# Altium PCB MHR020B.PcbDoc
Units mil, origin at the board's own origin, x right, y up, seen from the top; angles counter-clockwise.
Board outline 3200 x 2500 mil, 2 copper layers (Top Layer, Bottom Layer), stack 62 mil thick; 118 components, 36 nets, 183 pads, 20 vias.
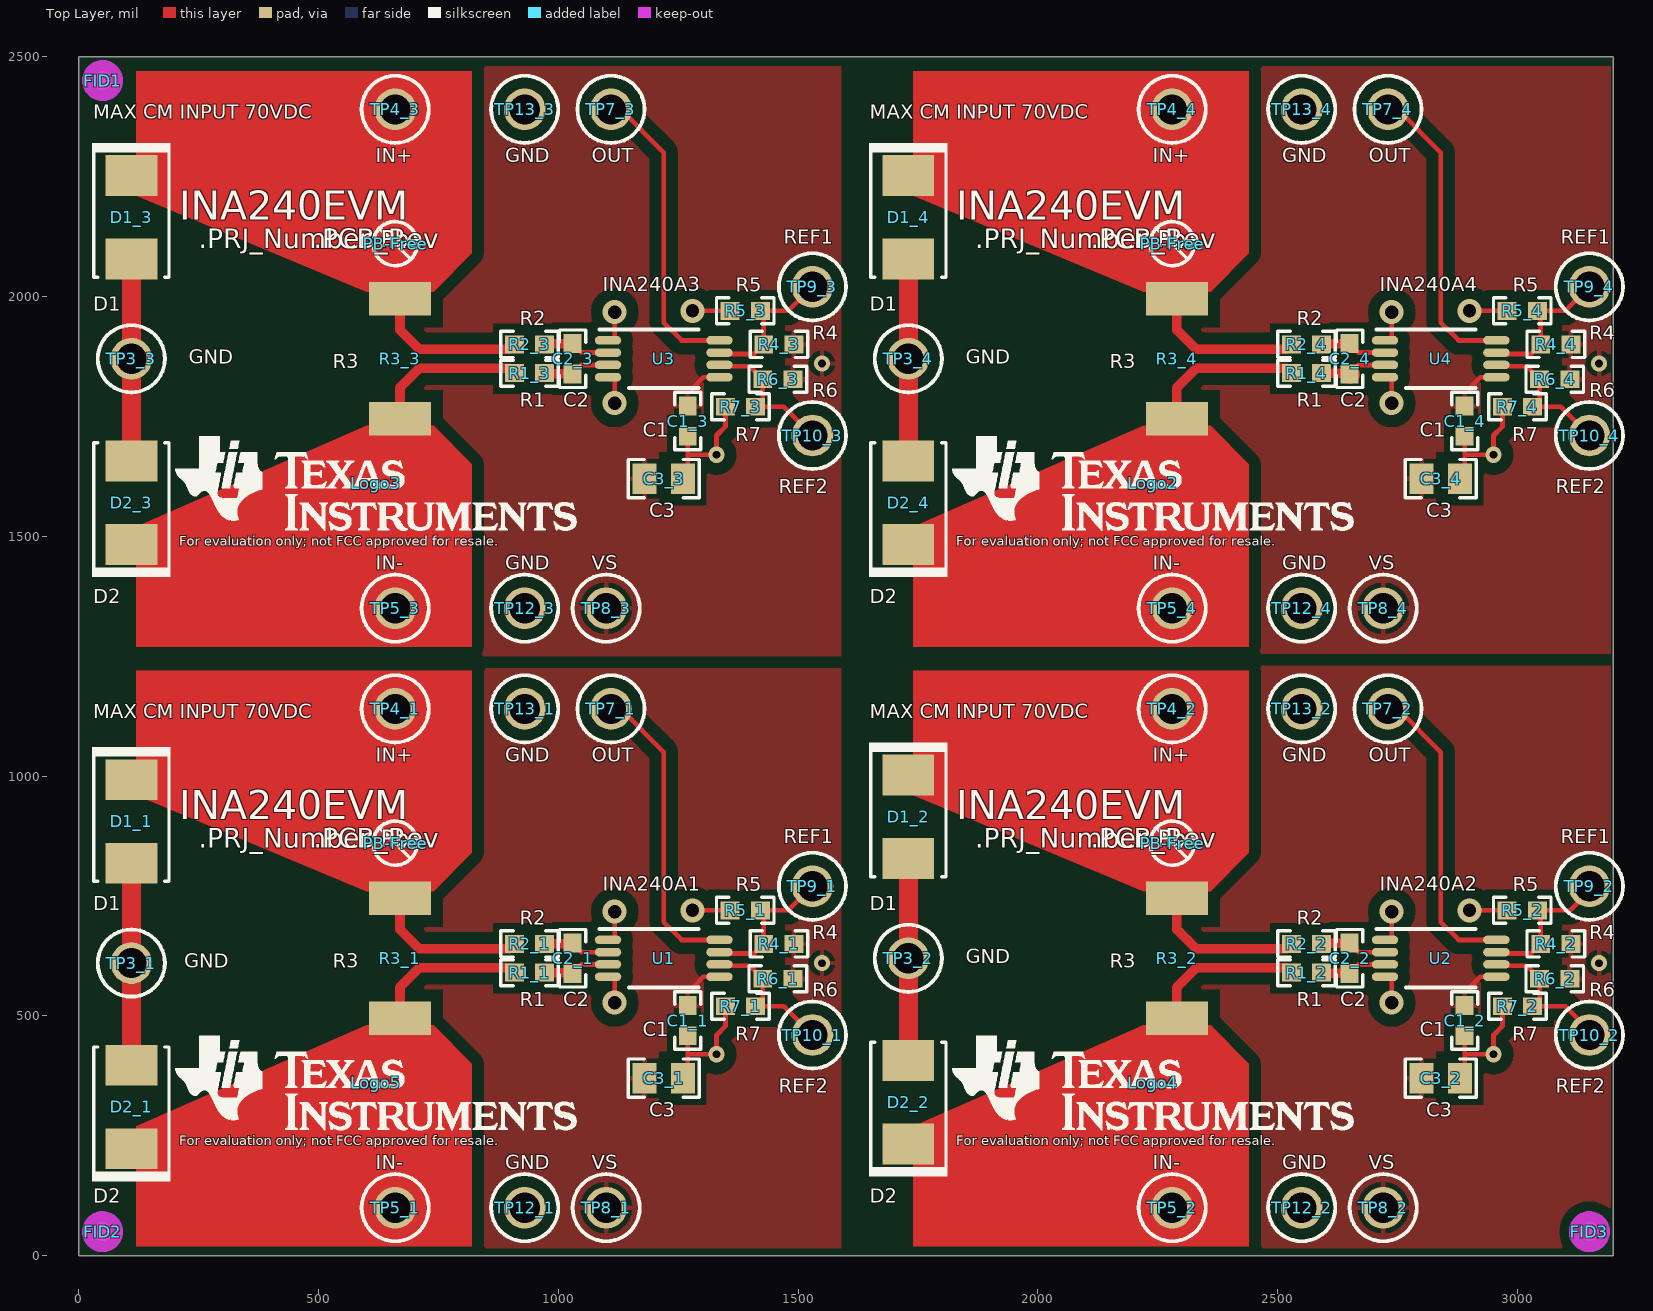
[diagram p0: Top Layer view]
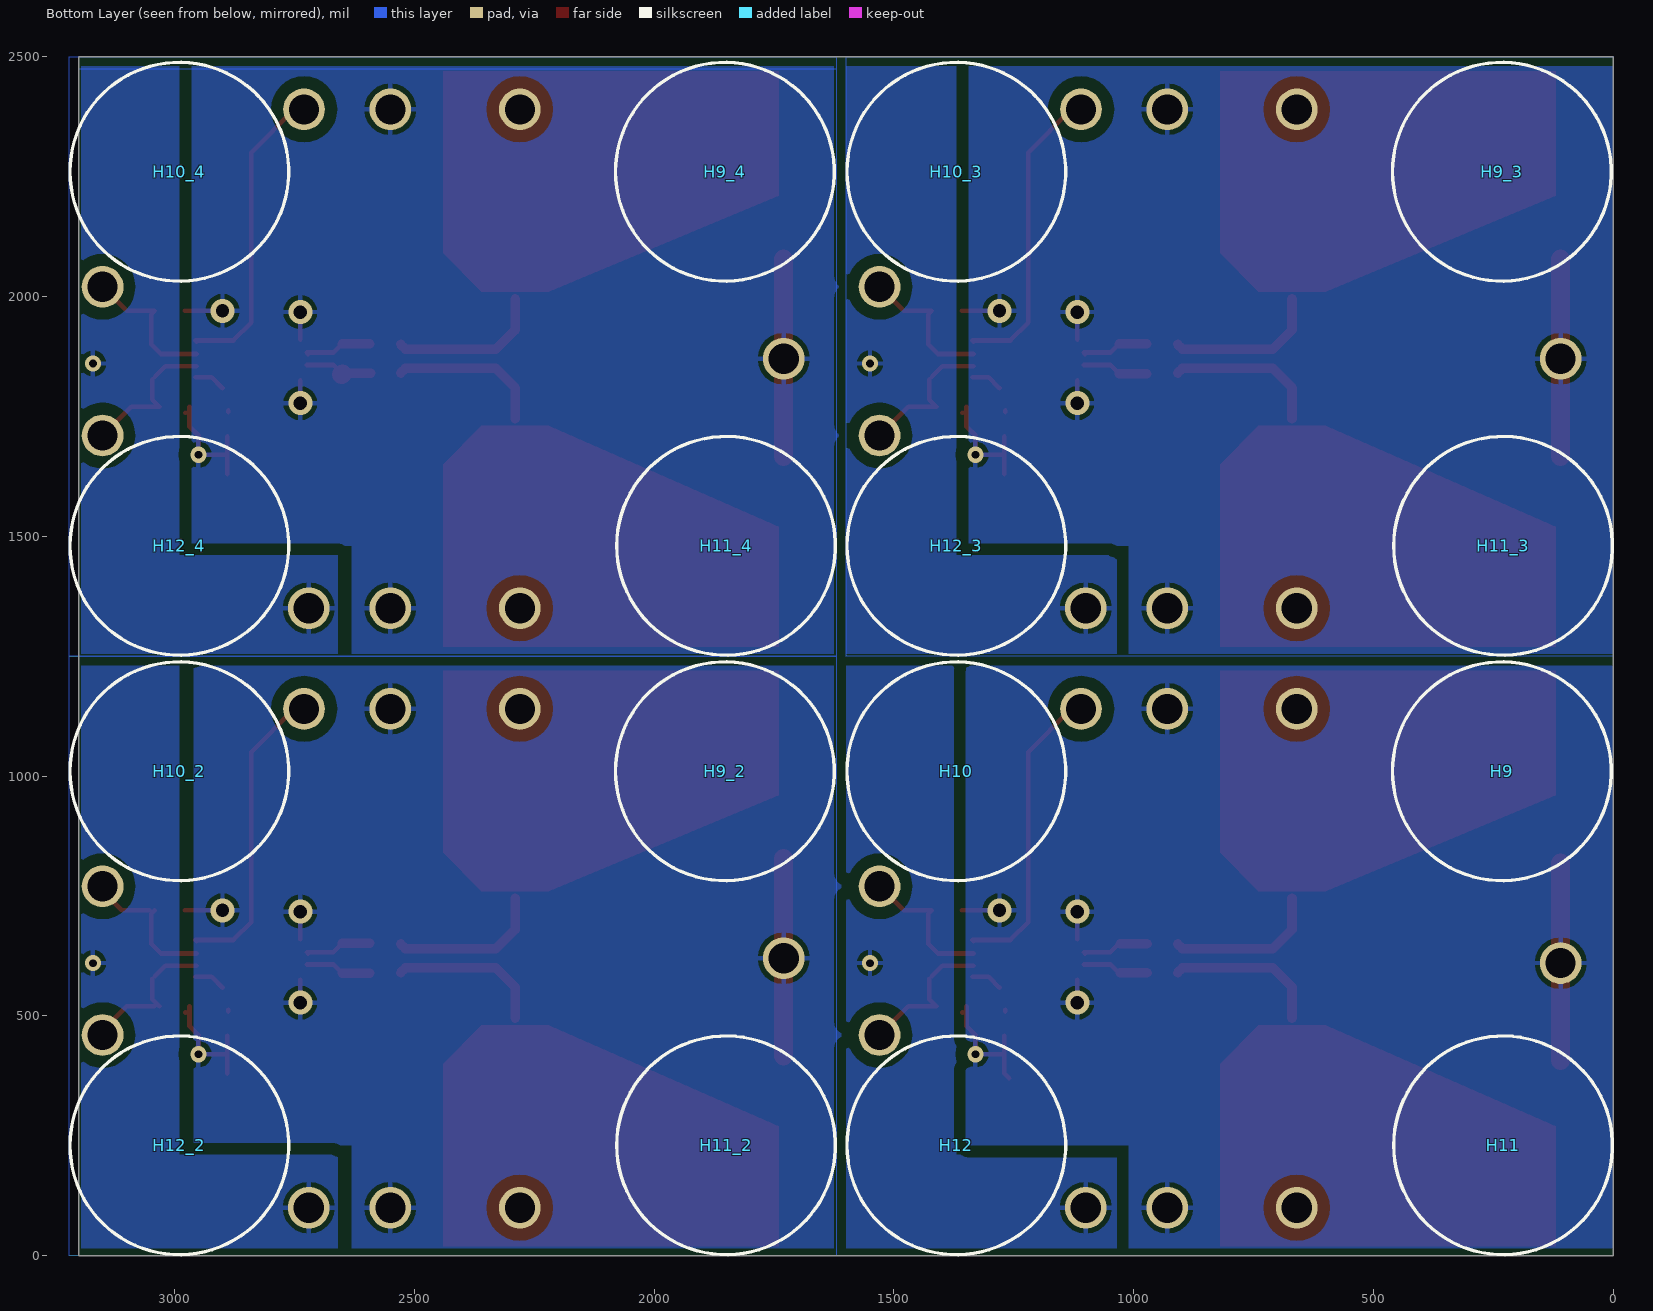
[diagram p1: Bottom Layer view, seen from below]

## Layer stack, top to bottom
Top Solder: solder mask 0.4, Solder Resist, Dk 3.5
Top Layer: signal copper 1.4
Dielectric1: core 59.2, FR-4, Dk 4.8
Bottom Layer: signal copper 1.4
Bottom Solder: solder mask 0.4, Solder Resist, Dk 3.5

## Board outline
0,0 3200,0 3200,2500 0,2500 0,0

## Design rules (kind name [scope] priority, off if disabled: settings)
AcuteAngle [All] p1: minimum=4.50000000000000E+0001 checktracksonly=FALSE
AssemblyTestPointUsage [All] p1: valid=2
Clearance Clearance_Keepouts [((IsTrack Or IsArc) And Not InPoly) And IsFree and IsKeepOut vs ((IsTrack Or IsArc) And Not InPoly) And IsFree and IsKeepOut] p1: gap=0
Clearance Clearance_BoardEdge_MountingHoles [OnCopper and InComponentClass('Mounting Holes') vs IsKeepOut] p2: gap=20
Clearance Clearance_BoardEdge_Poly [OnCopper and InPoly vs IsKeepOut] p3: gap=20
Clearance Clearance_BoardEdge [OnCopper and Not InComponentClass('Logo') and not InComponentClass('FiducialMark') and not InRegion(1000,500,4000,800) and Not IsKeepout vs IsKeepOut] p4: gap=20
Clearance Clearance_Poly [InPolygon] p5: gap=25
Clearance [All] p6: gap=7.87
ComponentClearance ComponentClearance_MountingHoles_FiducialMarks [InComponentClass('Mounting Holes') vs InComponentClass('FiducialMark')] p1: gap=10 collisioncheckmode=3 verticalgap=10 showdistances=FALSE
ComponentClearance ComponentClearance_Shunt [InComponentClass('Header') vs InComponentClass('Shunt')] p2: gap=0 collisioncheckmode=3 verticalgap=0 showdistances=FALSE
ComponentClearance ComponentClearance_Logo [InComponentClass('Logo')] p3: gap=10 collisioncheckmode=3 verticalgap=10 showdistances=FALSE
ComponentClearance ComponentClearance_ScrewToNut [(HasFootprint('NY PMS 440 0025 PH')) vs (HasFootprint('Keystone_1902C'))] p4: gap=5 collisioncheckmode=3 verticalgap=10 showdistances=FALSE
ComponentClearance ComponentClearance_MountingHoles [InComponentClass('Mounting Holes')] p5: gap=10 collisioncheckmode=3 verticalgap=100000 showdistances=FALSE
ComponentClearance ComponentClearance_SmallPassives [HasFootprint('0201*') or HasFootprint('0402*') or HasFootprint('0508') or HasFootprint('0603*') or HasFootprint('0612') or HasFootprint('0805*') or HasFootprint('0815*') or HasFootprint('0830*') or HasFootprint('1206*') or HasFootprint('1210*') or HasFootprint('1808*') or HasFootprint('1812*') or HasFootprint('1825*') or HasFootprint('2010*') or HasFootprint('2220*') or HasFootprint('2225*') or HasFootprint('2512*') or HasFootprint('2728*') or HasFootprint('3518*') vs HasFootprint('0201*') or HasFootprint('0402*') or HasFootprint('0508') or HasFootprint('0603*') or HasFootprint('0612') or HasFootprint('0805*') or HasFootprint('0815*') or HasFootprint('0830*') or HasFootprint('1206*') or HasFootprint('1210*') or HasFootprint('1808*') or HasFootprint('1812*') or HasFootprint('1825*') or HasFootprint('2010*') or HasFootprint('2220*') or HasFootprint('2225*') or HasFootprint('2512*') or HasFootprint('2728*') or HasFootprint('3518*')] p6: gap=20 collisioncheckmode=3 verticalgap=10 showdistances=FALSE
ComponentClearance ComponentClearance_THtoSMT [IsThruComponent vs IsSMTComponent] p7: gap=10 collisioncheckmode=3 verticalgap=30 showdistances=FALSE
ComponentClearance ComponentClearance_THtoTH [IsThruComponent vs IsThruComponent] p8: gap=20 collisioncheckmode=3 verticalgap=30 showdistances=FALSE
ComponentClearance [All] p9: gap=10 collisioncheckmode=3 verticalgap=10 showdistances=FALSE
DiffPairsRouting [All] p1: maxlimit=100 minlimit=10 mostfreqgap=10 toplayer_minwidth=15 toplayer_maxwidth=15 toplayer_prefwidth=15 bottomlayer_minwidth=15 bottomlayer_maxwidth=15 bottomlayer_prefwidth=15 maxuncoupledlength=1000
FabricationTestPointUsage TestPointUsage [All] p1: valid=2 allowmultiple=FALSE
FabricationTestpoint Testpoint [All] p1: side=3 testpointundercomponent=TRUE minsize=40 maxsize=100 preferedsize=60 minholesize=0 maxholesize=40 preferedholesize=32 testpointgrid=1 allowsidetop=TRUE allowsidebottom=TRUE usegrid=TRUE gridtolerance=0.01
FanoutControl Fanout_LCC [IsLCC] p1: bgadir=Out bgaviamode=Centered fanoutstyle=Auto fanoutdirection=Alternating viagrid=1 // Fanout_LCC (Default Rule)
FanoutControl Fanout_BGA [IsBGA] p2: bgadir=Out bgaviamode=Centered fanoutstyle=Auto fanoutdirection=Alternating viagrid=1 // Fanout_BGA (Default Rule)
FanoutControl Fanout_Default [All] p4: bgadir=Out bgaviamode=Centered fanoutstyle=Auto fanoutdirection=Alternating viagrid=1 // Fanout_Default (Default Rule)
FanoutControl Fanout_Small [(CompPinCount < 5)] p5: bgadir=Out bgaviamode=Centered fanoutstyle=Auto fanoutdirection=OutThenIn viagrid=1 // Fanout_Small (Default Rule)
HoleSize [All] p1: absolutevalues=TRUE maxlimit=251 minlimit=8 maxpercent=80.000 minpercent=20.000
MinimumAnnularRing MinimumAnnularRing_ThermalPadVias [IsVia and InAnyComponent] p1: minimumring=5.91
MinimumAnnularRing [All] p2: minimumring=9
MinimumSolderMaskSliver MinimumSolderMaskSliver_Logo [InComponentClass('Logo') vs InComponentClass('Logo')] p1: minsoldermaskwidth=0.7
MinimumSolderMaskSliver [All] p2: minsoldermaskwidth=3.94
PlaneConnect [All] p1: planeconnectstyle=Relief reliefexpansion=10 reliefentries=4 reliefconductorwidth=10 reliefairgap=10
PolygonConnect [All] p1: connectstyle=Relief reliefconductorwidth=10 reliefentries=4 polygonreliefangle="90 Angle" airgapwidth=10
RoutingVias ThermalPadVias [IsVia and InAnyComponent] p1: holewidth=7.87 width=19.68 viastyle="Through Hole" minholewidth=7.87 minwidth=19.68 maxholewidth=12.99 maxwidth=23.62
RoutingVias [All] p2: holewidth=16 width=34 viastyle="Through Hole" minholewidth=7.87 minwidth=26 maxholewidth=40 maxwidth=65
SilkToBoardRegionClearance [Not ((IsComment or IsDesignator) And (Hide <> 'False')) and not InRegion(1000,500,4000,800)] p1:
SilkToSilkClearance SilkToSilkClearance_Pb-FreeLogo [(HasFootprint('Pb-Free_Overlay_Medium') OR HasFootprint('Pb-Free_Overlay_Small')) vs (HasFootprint('Pb-Free_Overlay_Medium') OR HasFootprint('Pb-Free_Overlay_Small'))] p1: silktosilkclearance=0
SilkToSilkClearance [All] p2: silktosilkclearance=5
SilkToSolderMaskClearance "Silk to Solder Mask Opening" [All] p1: minsilkscreentomaskgap=3 clearancetoexposedcopper=FALSE
SolderMaskExpansion [All] p1: expansion=1.97
Width [All] p1: maxlimit=100 minlimit=10 preferedwidth=10
15 further rules are at their usual default settings.

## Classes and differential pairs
component class MHR020A_Hardware: FID1 FID2 FID3 H9 H9_2 H9_3 H9_4 H10 H10_2 H10_3 H10_4 H11 H11_2 H11_3 H11_4 H12 H12_2 H12_3 H12_4 Logo2 Logo3 Logo4 Logo5 PB-Free ZZ2 ZZ3 ZZ4
component class FiducialMark: FID1 FID2 FID3
component class AssemblyNote: ZZ2 ZZ3 ZZ4
component class Logo: Logo2 Logo3 Logo4 Logo5
component class MHR020A: C1_1 C1_2 C1_3 C1_4 C2_1 C2_2 C2_3 C2_4 C3_1 C3_2 C3_3 C3_4 D1_1 D1_2 D1_3 D1_4 D2_1 D2_2 D2_3 D2_4 R1_1 R1_2 R1_3 R1_4 R2_1 R2_2 R2_3 R2_4 R3_1 R3_2 R3_3 R3_4 R4_1 R4_2 R4_3 R4_4 R5_1 R5_2 R5_3 R5_4 R6_1 R6_2 R6_3 R6_4 R7_1 R7_2 R7_3 R7_4 TP3_1 TP3_2 TP3_3 TP3_4 TP4_1 TP4_2 TP4_3 TP4_4 TP5_1 TP5_2 TP5_3 TP5_4 TP7_1 TP7_2 TP7_3 TP7_4 TP8_1 TP8_2 TP8_3 TP8_4 TP9_1 TP9_2 TP9_3 TP9_4 TP10_1 TP10_2 TP10_3 TP10_4 TP12_1 TP12_2 TP12_3 TP12_4 TP13_1 TP13_2 TP13_3 TP13_4 U1 U2 U3 U4

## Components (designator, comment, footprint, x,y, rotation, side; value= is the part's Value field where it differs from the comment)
C1_1 "0603YC104JAT2A" 0603 1270,490 r270 top
C1_2 "0603YC104JAT2A" 0603 2890,490 r270 top
C1_3 "0603YC104JAT2A" 0603 1270,1740 r270 top
C1_4 "0603YC104JAT2A" 0603 2890,1740 r270 top
C2_1 "0603YC104JAT2A" 0603 1030,620 r90 top
C2_2 "0603YC104JAT2A" 0603 2650,620 r90 top
C2_3 "0603YC104JAT2A" 0603 1030,1870 r90 top
C2_4 "0603YC104JAT2A" 0603 2650,1870 r90 top
C3_1 "08053D105KAT2A" 0805_HV 1220,370 r0 top
C3_2 "08053D105KAT2A" 0805_HV 2840,370 r0 top
C3_3 "08053D105KAT2A" 0805_HV 1220,1620 r0 top
C3_4 "08053D105KAT2A" 0805_HV 2840,1620 r0 top
D1_1 "SMBJ70A-13-F" SMB 110,905.27 r270 top
D1_2 "SMBJ70A-13-F" SMB 1730,915.27 r270 top
D1_3 "SMBJ70A-13-F" SMB 110,2165.27 r270 top
D1_4 "SMBJ70A-13-F" SMB 1730,2165.27 r270 top
D2_1 "SMBJ70A-13-F" SMB 110,310 r90 top
D2_2 "SMBJ70A-13-F" SMB 1730,320 r90 top
D2_3 "SMBJ70A-13-F" SMB 110,1570 r90 top
D2_4 "SMBJ70A-13-F" SMB 1730,1570 r90 top
FID1 "Fiducial" Fiducial10-20 50,2450 r0 top
FID2 "Fiducial" Fiducial10-20 50,50 r0 top
FID3 "Fiducial" Fiducial10-20 3150,50 r0 top
H9 "SJ-5303 (CLEAR)" Bumpon_SJ5003Transparent 232.5,1010 r180 bottom
H9_2 "SJ-5303 (CLEAR)" Bumpon_SJ5003Transparent 1852.5,1010 r180 bottom
H9_3 "SJ-5303 (CLEAR)" Bumpon_SJ5003Transparent 232.5,2260 r180 bottom
H9_4 "SJ-5303 (CLEAR)" Bumpon_SJ5003Transparent 1852.5,2260 r180 bottom
H10 "SJ-5303 (CLEAR)" Bumpon_SJ5003Transparent 1370,1010 r180 bottom
H10_2 "SJ-5303 (CLEAR)" Bumpon_SJ5003Transparent 2990,1010 r180 bottom
H10_3 "SJ-5303 (CLEAR)" Bumpon_SJ5003Transparent 1370,2260 r180 bottom
H10_4 "SJ-5303 (CLEAR)" Bumpon_SJ5003Transparent 2990,2260 r180 bottom
H11 "SJ-5303 (CLEAR)" Bumpon_SJ5003Transparent 230,230 r180 bottom
H11_2 "SJ-5303 (CLEAR)" Bumpon_SJ5003Transparent 1850,230 r180 bottom
H11_3 "SJ-5303 (CLEAR)" Bumpon_SJ5003Transparent 230,1480 r180 bottom
H11_4 "SJ-5303 (CLEAR)" Bumpon_SJ5003Transparent 1850,1480 r180 bottom
H12 "SJ-5303 (CLEAR)" Bumpon_SJ5003Transparent 1370,230 r180 bottom
H12_2 "SJ-5303 (CLEAR)" Bumpon_SJ5003Transparent 2990,230 r180 bottom
H12_3 "SJ-5303 (CLEAR)" Bumpon_SJ5003Transparent 1370,1480 r180 bottom
H12_4 "SJ-5303 (CLEAR)" Bumpon_SJ5003Transparent 2990,1480 r180 bottom
Logo2 "Texas Instruments" TI_Stacked_Overlay_Small 2240,1610 r0 top
Logo3 "Texas Instruments" TI_Stacked_Overlay_Small 620,1610 r0 top
Logo4 "Texas Instruments" TI_Stacked_Overlay_Small 2240,360 r0 top
Logo5 "Texas Instruments" TI_Stacked_Overlay_Small 620,360 r0 top
PB-Free "Pb-Free Symbol" Pb-Free_Overlay_Small 2280,2110 r0 top
PB-Free "Pb-Free Symbol" Pb-Free_Overlay_Small 660,2110 r0 top
PB-Free "Pb-Free Symbol" Pb-Free_Overlay_Small 2280,860 r0 top
PB-Free "Pb-Free Symbol" Pb-Free_Overlay_Small 660,860 r0 top
R1_1 "ERJ-3GEY0R00V" 0603 940,590 r0 top
R1_2 "ERJ-3GEY0R00V" 0603 2560,590 r0 top
R1_3 "ERJ-3GEY0R00V" 0603 940,1840 r0 top
R1_4 "ERJ-3GEY0R00V" 0603 2560,1840 r0 top
R2_1 "ERJ-3GEY0R00V" 0603 940,650 r0 top
R2_2 "ERJ-3GEY0R00V" 0603 2560,650 r0 top
R2_3 "ERJ-3GEY0R00V" 0603 940,1900 r0 top
R2_4 "ERJ-3GEY0R00V" 0603 2560,1900 r0 top
R3_1 "STD" R2512 670,620 r270 top
R3_2 "STD" R2512 2290,620 r270 top
R3_3 "STD" R2512 670,1870 r270 top
R3_4 "STD" R2512 2290,1870 r270 top
R4_1 "ERJ-3GEY0R00V" 0603 1460,650 r180 top
R4_2 "ERJ-3GEY0R00V" 0603 3080,650 r180 top
R4_3 "ERJ-3GEY0R00V" 0603 1460,1900 r180 top
R4_4 "ERJ-3GEY0R00V" 0603 3080,1900 r180 top
R5_1 "ERJ-3GEY0R00V" 0603 1390,720 r180 top
R5_2 "ERJ-3GEY0R00V" 0603 3010,720 r180 top
R5_3 "ERJ-3GEY0R00V" 0603 1390,1970 r180 top
R5_4 "ERJ-3GEY0R00V" 0603 3010,1970 r180 top
R6_1 "ERJ-3GEY0R00V" 0603 1457.81,577.34 r180 top
R6_2 "ERJ-3GEY0R00V" 0603 3077.81,577.34 r180 top
R6_3 "ERJ-3GEY0R00V" 0603 1457.81,1827.34 r180 top
R6_4 "ERJ-3GEY0R00V" 0603 3077.81,1827.34 r180 top
R7_1 "ERJ-3GEY0R00V" 0603 1380,520 r180 top
R7_2 "ERJ-3GEY0R00V" 0603 3000,520 r180 top
R7_3 "ERJ-3GEY0R00V" 0603 1380,1770 r180 top
R7_4 "ERJ-3GEY0R00V" 0603 3000,1770 r180 top
TP3_1 "5012" Keystone5012 110,610 r90 top
TP3_2 "5012" Keystone5012 1730,620 r90 top
TP3_3 "5012" Keystone5012 110,1870 r90 top
TP3_4 "5012" Keystone5012 1730,1870 r90 top
TP4_1 "5012" Keystone5012 660,1140 r90 top
TP4_2 "5012" Keystone5012 2280,1140 r90 top
TP4_3 "5012" Keystone5012 660,2390 r90 top
TP4_4 "5012" Keystone5012 2280,2390 r90 top
TP5_1 "5012" Keystone5012 660,100 r90 top
TP5_2 "5012" Keystone5012 2280,100 r90 top
TP5_3 "5012" Keystone5012 660,1350 r90 top
TP5_4 "5012" Keystone5012 2280,1350 r90 top
TP7_1 "5012" Keystone5012 1110,1140 r90 top
TP7_2 "5012" Keystone5012 2730,1140 r90 top
TP7_3 "5012" Keystone5012 1110,2390 r90 top
TP7_4 "5012" Keystone5012 2730,2390 r90 top
TP8_1 "5012" Keystone5012 1100,100 r90 top
TP8_2 "5012" Keystone5012 2720,100 r90 top
TP8_3 "5012" Keystone5012 1100,1350 r90 top
TP8_4 "5012" Keystone5012 2720,1350 r90 top
TP9_1 "5012" Keystone5012 1530,770 r90 top
TP9_2 "5012" Keystone5012 3150,770 r90 top
TP9_3 "5012" Keystone5012 1530,2020 r90 top
TP9_4 "5012" Keystone5012 3150,2020 r90 top
TP10_1 "5012" Keystone5012 1530,460 r90 top
TP10_2 "5012" Keystone5012 3150,460 r90 top
TP10_3 "5012" Keystone5012 1530,1710 r90 top
TP10_4 "5012" Keystone5012 3150,1710 r90 top
TP12_1 "5012" Keystone5012 930,100 r90 top
TP12_2 "5012" Keystone5012 2550,100 r90 top
TP12_3 "5012" Keystone5012 930,1350 r90 top
TP12_4 "5012" Keystone5012 2550,1350 r90 top
TP13_1 "5012" Keystone5012 930,1140 r90 top
TP13_2 "5012" Keystone5012 2550,1140 r90 top
TP13_3 "5012" Keystone5012 930,2390 r90 top
TP13_4 "5012" Keystone5012 2550,2390 r90 top
U1 "INA240A1PW" PW0008A_N 1220,620 r0 top
U2 "INA240A2PW" PW0008A_N 2840,620 r0 top
U3 "INA240A3PW" PW0008A_N 1220,1870 r0 top
U4 "INA240A4PW" PW0008A_N 2840,1870.01 r0 top
ZZ2 "These assemblies are ESD sensitive, ESD precautions shall be observed." AssemblyNote 185,3829.11 r0 top
ZZ3 "These assemblies must be clean and free from flux and all contaminants. Use of no clean flux is not acceptable." AssemblyNote 185,3740.56 r0 top
ZZ4 "These assemblies must comply with workmanship standards IPC-A-610 Class 2, unless otherwise specified." AssemblyNote 185,3652 r0 top

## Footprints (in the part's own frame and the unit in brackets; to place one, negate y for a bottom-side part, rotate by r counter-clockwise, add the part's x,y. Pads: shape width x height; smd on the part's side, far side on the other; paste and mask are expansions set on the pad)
0603 [mm] "0603 from SM-752 data"
  rect 1x0.95 smd: 1(-0.8,0) 2(0.8,0)
  silkscreen extent -1.52,-0.69 1.52,0.69, body extent -0.87,-0.47 0.87,0.47, height 0.85
0805_HV [mil] "0805 with 30mil clearance between pads"
  rect 50x63 smd: 1(-40,0) 2(40,0)
  silkscreen extent -74,-40 74,40, body extent -43,-29 43,29, height 57
AssemblyNote [mil] "Assembly Note"
Bumpon_SJ5003Transparent [mil] "3M Hemispherical Bumpon transparent"
  round 1 on Mech4: 0(0,0)
  silkscreen extent -228,-228 228,228, body extent -219,-218 219,218, height 197
Fiducial10-20 [mm]
  round 1 smd mask+0.5: 1(0,0)
  Top Layer keep-out circle w1.178: c0,0 r0.5
Keystone5012 [mil] "Keystone Multipurpose loops"
  round 87 hole 63: 1(0,0)
  silkscreen extent -70,-70 70,70, body extent -63,-63 63,62, height 319
Pb-Free_Overlay_Small [mil]
  silkscreen extent -46,-46 46,46
PW0008A_N [mm] "TSOP, 8-Leads, Body 3x4.4mm, Pitch 0.65mm, IPC Medium Density"
  oval 1.4x0.45 smd: 1(-2.95,0.975) 2(-2.95,0.325) 3(-2.95,-0.325) 4(-2.95,-0.975) 5(2.95,-0.975) 6(2.95,-0.325) 7(2.95,0.325) 8(2.95,0.975)
  silkscreen extent -3.4,-1.55 1.85,1.55, body extent -3.21,-1.5 3.21,1.5, height 1.2
R2512 [mil]
  rect 70x130 smd: 1(-125,0) 2(125,0)
SMB [mil] "Molded Diode, 2-Leads, Body 5.4x3.6mm, IPC Medium Density, based on OnSemi component dimensions"
  rect 85x107.99 smd: 1(-87.01,0) 2(87.01,0)
  silkscreen extent -155,-82 125,82, body extent -106,-71 106,71, height 91
TI_Stacked_Overlay_Small [mil]
  silkscreen extent -418,-98 418,98

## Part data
C1_1 C1_2 C1_3 C1_4 C2_1 C2_2 C2_3 C2_4: "CAP, CERM, 0.1 µF, 16 V, +/- 5%, X7R, 0603"
C3_1 C3_2 C3_3 C3_4: "CAP, CERM, 1 µF, 25 V, +/- 10%, X5R, 0805"
D1_1 D1_2 D1_3 D1_4 D2_1 D2_2 D2_3 D2_4: "Diode, TVS, Uni, 70 V, 600 W, SMB"
FID1 FID2 FID3: "Fiducial mark.  There is nothing to buy or mount."
H9 H9_2 H9_3 H9_4 H10 H10_2 H10_3 H10_4 H11 H11_2 H11_3 H11_4 H12 H12_2 H12_3 H12_4: "Bumpon, Hemisphere, 0.44 X 0.20, Clear"
Logo2 Logo3 Logo4 Logo5: library part TI_Logo, "Texas Instrument Corporate Signature"
PB-Free PB-Free PB-Free PB-Free: library part Pb-Free
R1_1 R1_2 R1_3 R1_4 R2_1 R2_2 R2_3 R2_4 R4_1 R4_2 R4_3 R4_4 R5_1 R5_2 R5_3 R5_4 R6_1 R6_2 R6_3 R6_4 R7_1 R7_2 R7_3 R7_4: "RES, 0, 5%, 0.1 W, 0603"
R3_1 R3_2 R3_3 R3_4: library part R2512, "Resistor,  xx milliOhm, 1W, yy%"
TP3_1 TP3_2 TP3_3 TP3_4 TP4_1 TP4_2 TP4_3 TP4_4 TP5_1 TP5_2 TP5_3 TP5_4 TP7_1 TP7_2 TP7_3 TP7_4 TP8_1 TP8_2 TP8_3 TP8_4 TP9_1 TP9_2 TP9_3 TP9_4 TP10_1 TP10_2 TP10_3 TP10_4 TP12_1 TP12_2 TP12_3 TP12_4 TP13_1 TP13_2 TP13_3 TP13_4: "Test Point, Multipurpose, White, TH"
U1 U2 U3 U4: "Wide Common-Mode Range, Voltage Output, High or Low-Side Bi-Directional Zero-Drift Current Shunt Monitor, PW0008A"
ZZ2 ZZ3 ZZ4: library part AssemblyNote

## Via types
v1: diameter 50, hole 28, Top Layer to Bottom Layer, 12 vias
v2: diameter 34, hole 16, Top Layer to Bottom Layer, 8 vias

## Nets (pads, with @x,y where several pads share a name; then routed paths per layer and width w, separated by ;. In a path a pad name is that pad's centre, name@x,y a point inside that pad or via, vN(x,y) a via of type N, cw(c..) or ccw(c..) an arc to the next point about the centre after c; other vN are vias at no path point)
A1_P2: C2_1.2 R2_1.2 U1.2 | length 147.9
  Top Layer w10: C2_1.2@1028.5,650 C2_1.2 ; C2_1.2@1030,648.05 C2_1.2 ; U1.2@1101.67,630.14 U1.2@1099.01,632.8 ; U1.2 U1.2@1099.01,632.8 ; C2_1.2 1048.7,632.8 U1.2@1099.01,632.8
  Top Layer w20: R2_1.2 C2_1.2@1028.5,650
A1_P3: C2_1.1 R1_1.2 U1.3 | length 138.6
  Top Layer w10: C2_1.1 1048.7,607.2 U1.3
  Top Layer w20: R1_1.2 C2_1.1@1028.5,590
A1_P6: R6_1.2 R7_1.1 TP10_1.1 U1.6 | length 302
  Top Layer w10: U1.6@1333.96,604.54 1399.11,604.54 R6_1.2@1420.32,583.34 ; R6_1.2 1426.32,534.82 R7_1.1 1470,520 TP10_1.1
A1_P7: R4_1.2 R5_1.1 TP9_1.1 U1.7 | length 304.9
  Top Layer w10: U1.7@1333.96,630.14 1408.64,630.14 R4_1.2 1428.5,712.99 R5_1.1 1480,720 TP9_1.1
A1_P8: TP7_1.1 U1.8 | length 616.7
  Top Layer w10: TP7_1.1@1130,1140 1220,1050 1220,695.5 1257.11,658.39 U1.8 U1.8@1333.72,655.96
A2_P2: C2_2.2 R2_2.2 U2.2 | length 144.5
  Top Layer w10: C2_2.2@2648.5,650 C2_2.2 2668.7,632.8 U2.2@2719.01,632.8 ; U2.2@2721.67,630.14 U2.2@2719.01,632.8 ; U2.2 U2.2@2719.01,632.8
  Top Layer w20: R2_2.2@2592.99,651.5 C2_2.2
A2_P3: C2_2.1 R1_2.2 U2.3 | length 138.6
  Top Layer w10: C2_2.1 2668.7,607.2 U2.3
  Top Layer w20: R1_2.2@2592.99,588.5 C2_2.1
A2_P6: R6_2.2 R7_2.1 TP10_2.1 U2.6 | length 302
  Top Layer w10: U2.6@2953.96,604.54 3019.11,604.54 R6_2.2@3040.32,583.34 ; R7_2.1 3046.32,534.82 R6_2.2 ; R7_2.1@3041.5,520 3100,520 TP10_2.1@3160,460
A2_P7: R4_2.2 R5_2.1 TP9_2.1 U2.7 | length 304.9
  Top Layer w10: U2.7@2953.96,630.14 3028.64,630.14 R4_2.2 3048.5,712.99 R5_2.1 ; R5_2.1@3051.5,720 3110,720 TP9_2.1@3160,770
A2_P8: TP7_2.1 U2.8 | length 616.7
  Top Layer w10: TP7_2.1@2750,1140 2840,1050 2840,695.5 2877.11,658.39 U2.8 U2.8@2953.72,655.96
A3_P2: C2_3.2 R2_3.2 U3.2 | length 142.4
  Top Layer w10: C2_3.2 1048.7,1882.8 U3.2@1099.01,1882.8 ; U3.2@1101.67,1880.14 U3.2@1099.01,1882.8 ; U3.2 U3.2@1099.01,1882.8
  Top Layer w20: R2_3.2@972.99,1901.5 C2_3.2
A3_P3: C2_3.1 R1_3.2 U3.3 | length 138.6
  Top Layer w10: C2_3.1 1048.7,1857.2 U3.3
  Top Layer w20: R1_3.2@972.99,1838.5 C2_3.1
A3_P6: R6_3.2 R7_3.1 TP10_3.1 U3.6 | length 302
  Top Layer w10: U3.6@1333.96,1854.54 1399.11,1854.54 R6_3.2@1420.32,1833.34 ; R6_3.2 1426.32,1784.82 R7_3.1 1470,1770 TP10_3.1
A3_P7: R4_3.2 R5_3.1 TP9_3.1 U3.7 | length 304.9
  Top Layer w10: U3.7@1333.96,1880.14 1408.64,1880.14 R4_3.2 1428.5,1962.99 R5_3.1 1480,1970 TP9_3.1
A3_P8: TP7_3.1 U3.8 | length 616.7
  Top Layer w10: TP7_3.1@1130,2390 1220,2300 1220,1945.5 1257.11,1908.39 U3.8 U3.8@1333.72,1905.96
A4_P2: C2_4.2 R2_4.2 U4.2 | length 142.4
  Top Layer w10: C2_4.2 2668.7,1882.8 U4.2@2719.01,1882.8 ; U4.2@2721.67,1880.14 U4.2@2719.01,1882.8 ; U4.2 U4.2@2719.01,1882.8
  Top Layer w20: R2_4.2@2592.99,1901.5 C2_4.2
A4_P3: C2_4.1 R1_4.2 U4.3 | length 140.7
  Top Layer w10: C2_4.1 2668.7,1857.2 U4.3
  Top Layer w20: R1_4.2 C2_4.1@2648.5,1840
  Top Layer w40: C2_4.1 C2_4.1@2651.5,1837.01
A4_P6: R6_4.2 R7_4.1 TP10_4.1 U4.6 | length 302
  Top Layer w10: U4.6@2953.96,1854.54 3019.11,1854.54 R6_4.2@3040.32,1833.34 ; R6_4.2 3046.32,1784.82 R7_4.1 3090,1770 TP10_4.1
A4_P7: R4_4.2 R5_4.1 TP9_4.1 U4.7 | length 304.9
  Top Layer w10: U4.7@2953.96,1880.14 3028.64,1880.14 R4_4.2 3048.5,1962.99 R5_4.1 3100,1970 TP9_4.1
A4_P8: TP7_4.1 U4.8 | length 616.7
  Top Layer w10: TP7_4.1@2750,2390 2840,2300 2840,1945.5 2877.11,1908.39 U4.8 U4.8@2953.72,1905.96
GND: C1_1.2 C3_1.2 D1_1.2 D2_1.2 R5_1.2 R7_1.2 TP3_1.1 TP12_1.1 TP13_1.1 U1.1 U1.4 | length 836.2
  Top Layer w10: v1(1117.81,527.34) U1.4@1117.81,575.1 ; U1.1@1117.81,659.58 v1(1117.81,717.34) ; C3_1.2 1270,380 1270,420 ; C1_1.2 1270,420 ; v1@1300,720 R5_1.2 ; R7_1.2 1348.5,478.5 1330,460 v2(1330,420) 1270,420 ; R7_1.2@1357.06,507.28 R7_1.2@1357.33,507.55
  Top Layer w40: D2_1.2@110,406.76 TP3_1.1 D1_1.2
  other v1: 1280,720
GND2: C1_2.2 C3_2.2 D1_2.2 D2_2.2 R5_2.2 R7_2.2 TP3_2.1 TP12_2.1 TP13_2.1 U2.1 U2.4 | length 821.3
  Top Layer w10: v1(2737.81,527.34) U2.4@2737.81,575.1 ; U2.1@2737.81,659.58 v1(2737.81,717.34) ; C3_2.2@2890,380 C1_2.2 ; 2890.75,420 v2(2950,420) 2950,460 2968.5,478.5 R7_2.2 ; v1@2920,720 R5_2.2 ; R7_2.2@2977.06,507.28 R7_2.2@2977.33,507.55
  Top Layer w40: D2_2.2@1730,416.76 TP3_2.1 D1_2.2
  other v1: 2900,720
GND3: C1_3.2 C3_3.2 D1_3.2 D2_3.2 R5_3.2 R7_3.2 TP3_3.1 TP12_3.1 TP13_3.1 U3.1 U3.4 | length 821.3
  Top Layer w10: v1(1117.81,1777.34) U3.4@1117.81,1825.1 ; U3.1@1117.81,1909.58 v1(1117.81,1967.34) ; C3_3.2@1270,1630 C1_3.2 ; 1270.75,1670 v2(1330,1670) 1330,1710 1348.5,1728.5 R7_3.2 ; v1@1300,1970 R5_3.2 ; R7_3.2@1357.06,1757.28 R7_3.2@1357.33,1757.55
  Top Layer w40: D2_3.2@110,1666.76 TP3_3.1 D1_3.2
  other v1: 1280,1970
GND4: C1_4.2 C3_4.2 D1_4.2 D2_4.2 R5_4.2 R7_4.2 TP3_4.1 TP12_4.1 TP13_4.1 U4.1 U4.4 | length 822.1
  Top Layer w10: v1(2737.81,1777.34) U4.4@2737.81,1825.1 ; U4.1@2737.81,1909.58 v1(2737.81,1967.34) ; C3_4.2@2890,1630 2890,1670 ; C1_4.2 2890,1670 ; v1@2920,1970 R5_4.2 ; R7_4.2 2968.5,1728.5 2950,1710 v2(2950,1670) 2890,1670 ; R7_4.2@2977.06,1757.28 R7_4.2@2977.33,1757.55
  Top Layer w40: D2_4.2@1730,1666.76 TP3_4.1 D1_4.2
  other v1: 2900,1970
INN: D2_1.1 R1_1.1 R3_1.2 TP5_1.1 | length 324.2
  Top Layer w20: R3_1.2 670,560 710,600 898.5,600 R1_1.1
INN4: D2_4.1 R1_4.1 R3_4.2 TP5_4.1 | length 324.2
  Top Layer w20: R3_4.2 2290,1810 2330,1850 2518.5,1850 R1_4.1
INN_2: D2_2.1 R1_2.1 R3_2.2 TP5_2.1 | length 324.2
  Top Layer w20: R3_2.2 2290,560 2330,600 2518.5,600 R1_2.1
INP: D1_1.1 R2_1.1 R3_1.1 TP4_1.1 | length 324.2
  Top Layer w20: R3_1.1 670,680 710,640 898.5,640 R2_1.1
INP3: D1_3.1 R2_3.1 R3_3.1 TP4_3.1 | length 324.2
  Top Layer w20: R3_3.1 670,1930 710,1890 898.5,1890 R2_3.1
INP4: D1_4.1 R2_4.1 R3_4.1 TP4_4.1 | length 324.2
  Top Layer w20: R3_4.1 2290,1930 2330,1890 2518.5,1890 R2_4.1
INP_2: D1_2.1 R2_2.1 R3_2.1 TP4_2.1 | length 324.2
  Top Layer w20: R3_2.1 2290,680 2330,640 2518.5,640 R2_2.1
NetD2_3_1: D2_3.1 R1_3.1 R3_3.2 TP5_3.1 | length 324.2
  Top Layer w20: R3_3.2 670,1810 710,1850 898.5,1850 R1_3.1
VCC: C1_1.1 C3_1.1 R4_1.1 R6_1.1 TP8_1.1 U1.5 | length 69.5
  Top Layer w10: C1_1.1@1267.81,508.84 C1_1.1@1267.81,512.81 ; 1280,558.98 1302.64,581.61 U1.5
  other v2: 1550,610
VCC2: C1_2.1 C3_2.1 R4_2.1 R6_2.1 TP8_2.1 U2.5 | length 69.5
  Top Layer w10: C1_2.1@2887.81,508.84 C1_2.1@2887.81,512.81 ; 2900,558.98 2922.64,581.61 U2.5
  other v2: 3170,610
VCC3: C1_3.1 C3_3.1 R4_3.1 R6_3.1 TP8_3.1 U3.5 | length 69.5
  Top Layer w10: C1_3.1@1267.81,1758.84 C1_3.1@1267.81,1762.81 ; 1280,1808.98 1302.64,1831.61 U3.5
  other v2: 1550,1860
VCC4: C1_4.1 C3_4.1 R4_4.1 R6_4.1 TP8_4.1 U4.5 | length 69.5
  Top Layer w10: C1_4.1@2887.81,1758.84 C1_4.1@2887.81,1762.81 ; 2900,1808.98 2922.64,1831.61 U4.5
  other v2: 3170,1860
pads on no net: FID1.1 FID2.1 FID3.1 H9.0 H9_2.0 H9_3.0 H9_4.0 H10.0 H10_2.0 H10_3.0 H10_4.0 H11.0 H11_2.0 H11_3.0 H11_4.0 H12.0 H12_2.0 H12_3.0 H12_4.0

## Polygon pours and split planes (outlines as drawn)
VCC4 on Bottom Layer "VCC4" (solid, remove dead copper, pour order 33): 2660,1250 3200,1250 3200,2480 2990,2480 2990,1460 2660,1460 2660,1250
VCC4 on Bottom Layer "VCC4" (solid, remove dead copper, shelved, pour order 29): 2650,1250 3200,1250 2500,1250
VCC3 on Bottom Layer "VCC3" (solid, remove dead copper, pour order 26): 1050,1250 1600,1250 1600,2480 1370,2480 1370,1460 1030,1460 1030,1250
VCC2 on Bottom Layer "VCC2" (solid, remove dead copper, pour order 23): 2660,0 3200,0 3200,1230 2990,1230 2990,210 2660,210 2660,0
VCC on Bottom Layer "VCC1" (solid, remove dead copper, pour order 20): 1050,0 1600,0 1600,1230 1370,1230 1370,210 1030,210 1030,0
GND on Bottom Layer "GND1" (solid, remove dead copper, pour order 19): 0,0 1010,0 1010,230 1350,230 1350,1230 0,1230
GND4 on Bottom Layer "GND4" (solid, remove dead copper, pour order 35): 1610,1250 2630,1250 2630,1480 2970,1480 2970,2480 1610,2480
GND3 on Bottom Layer "GND3" (solid, remove dead copper, pour order 30): 0,1250 1010,1250 1010,1480 1350,1480 1350,2480 0,2480
no net on Bottom Layer "Bottom Layer-No Net" (solid, remove dead copper, shelved, pour order 21): 0,1250 1600,1250 1600,2500 0,2500 0,1250
no net on Bottom Layer "Bottom Layer-No Net" (solid, remove dead copper, shelved, pour order 22): 1620,1250 3220,1250 3220,2500 1620,2500 1620,1250
no net on Bottom Layer "GND2" (solid, remove dead copper, shelved, pour order 27): 1620,1250 3200,1250 3200,2475 1620,2475 1620,1250
GND2 on Bottom Layer "GND2" (solid, remove dead copper, pour order 28): 1610,0 2630,0 2630,230 2960,230 2960,1230 1610,1230
no net on Bottom Layer "Bottom Layer-No Net" (solid, remove dead copper, shelved, pour order 24): 1620,0 3220,0 3220,1250 1620,1250 1620,0
VCC on Top Layer "VCC1" (solid, remove dead copper, pour order 36): 0,0 1590,0 1590,1230 0,1230 0,0
VCC4 on Top Layer "VCC4" (solid, remove dead copper, pour order 34): 1610,1250 3200,1250 3200,2480 1610,2480 1610,1250
VCC3 on Top Layer "VCC3" (solid, remove dead copper, pour order 32): 0,1250 1590,1250 1590,2480 0,2480 0,1250
VCC2 on Top Layer "VCC2" (solid, remove dead copper, pour order 25): 1610,0 3200,0 3200,1230 1610,1230 1610,0

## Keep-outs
Keep-Out Layer:
  text ".Layer_Name" at 577,-858.49 h60

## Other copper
Top Layer:
  region net NetD2_3_1: 120,1270 820,1270 820,1650 740,1730 600,1730 120,1520
  region net INP3: 600,2010 740,2010 820,2090 820,2470 120,2470 120,2210
  region net INP4: 2220,2010 2360,2010 2440,2090 2440,2470 1740,2470 1740,2210
  region net INN4: 1740,1270 2440,1270 2440,1650 2360,1730 2220,1730 1740,1520
  region net INN_2: 1740,20 2440,20 2440,400 2360,480 2220,480 1740,270
  region net INP_2: 2220,760 2360,760 2440,840 2440,1220 1740,1220 1740,960
  region net INP: 600,760 740,760 820,840 820,1220 120,1220 120,960
  region net INN: 120,20 820,20 820,400 740,480 600,480 120,270
  text ".Layer_Name" at 577,-858.49 h60
Bottom Layer:
  text ".Layer_Name" at 577,-858.49 h60

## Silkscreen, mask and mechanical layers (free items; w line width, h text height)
Top Overlay:
  text "MAX CM INPUT 70VDC" at 30,2370 h30
  text "MAX CM INPUT 70VDC" at 1650,2370 h30
  text "IN+" at 620,2280 h30
  text "GND" at 890,2280 h30
  text "OUT" at 1070,2280 h30
  text "IN+" at 2240,2280 h30
  text "GND" at 2510,2280 h30
  text "OUT" at 2690,2280 h30
  text "INA240EVM" at 210,2160 h60
  text "INA240EVM" at 1830,2160 h60
  text "REF1" at 1470,2110 h30
  text "REF1" at 3090,2110 h30
  text ".PRJ_Number" at 250,2100 h40
  text ".PCB_Rev" at 490,2100 h40
  text ".PRJ_Number" at 1870,2100 h40
  text ".PCB_Rev" at 2110,2100 h40
  text "INA240A3" at 1092.6,2011.02 h30
  text "INA240A4" at 2712.6,2011.02 h30
  text "R5" at 1370,2010 h30
  text "R5" at 2990,2010 h30
  text "D1" at 30,1970 h30
  text "D1" at 1650,1970 h30
  text "R2" at 920,1940 h30
  text "R2" at 2540,1940 h30
  text "R4" at 1530,1910 h30
  text "R4" at 3150,1910 h30
  text "GND" at 230,1860 h30
  text "GND" at 1850,1860 h30
  text "R3" at 530,1850 h30
  text "R3" at 2150,1850 h30
  text "R6" at 1530,1790 h30
  text "R6" at 3150,1790 h30
  text "R1" at 920,1770 h30
  text "C2" at 1010,1770 h30
  text "R1" at 2540,1770 h30
  text "C2" at 2630,1770 h30
  text "C1" at 1176.57,1707.51 h30
  text "C1" at 2796.57,1707.51 h30
  text "R7" at 1369.14,1698.08 h30
  text "R7" at 2989.14,1698.08 h30
  text "REF2" at 1460,1590 h30
  text "REF2" at 3080,1590 h30
  text "C3" at 1190,1540 h30
  text "C3" at 2810,1540 h30
  text "For evaluation only; not FCC approved for resale." at 210,1480 h20
  text "For evaluation only; not FCC approved for resale." at 1830,1480 h20
  text "IN-" at 620,1430 h30
  text "GND" at 890,1430 h30
  text "VS" at 1070,1430 h30
  text "IN-" at 2240,1430 h30
  text "GND" at 2510,1430 h30
  text "VS" at 2690,1430 h30
  text "D2" at 30,1360 h30
  text "D2" at 1650,1360 h30
  text "MAX CM INPUT 70VDC" at 30,1120 h30
  text "MAX CM INPUT 70VDC" at 1650,1120 h30
  text "IN+" at 620,1030 h30
  text "GND" at 890,1030 h30
  text "OUT" at 1070,1030 h30
  text "IN+" at 2240,1030 h30
  text "GND" at 2510,1030 h30
  text "OUT" at 2690,1030 h30
  text "INA240EVM" at 210,910 h60
  text "INA240EVM" at 1830,910 h60
  text "REF1" at 1470,860 h30
  text "REF1" at 3090,860 h30
  text ".PRJ_Number" at 250,850 h40
  text ".PCB_Rev" at 490,850 h40
  text ".PRJ_Number" at 1870,850 h40
  text ".PCB_Rev" at 2110,850 h40
  text "INA240A1" at 1092.6,761.02 h30
  text "INA240A2" at 2712.6,761.02 h30
  text "R5" at 1370,760 h30
  text "R5" at 2990,760 h30
  text "D1" at 30,720 h30
  text "D1" at 1650,720 h30
  text "R2" at 920,690 h30
  text "R2" at 2540,690 h30
  text "R4" at 1530,660 h30
  text "R4" at 3150,660 h30
  text "GND" at 1850,610 h30
  text "GND" at 220,600 h30
  text "R3" at 530,600 h30
  text "R3" at 2150,600 h30
  text "R6" at 1530,540 h30
  text "R6" at 3150,540 h30
  text "R1" at 920,520 h30
  text "C2" at 1010,520 h30
  text "R1" at 2540,520 h30
  text "C2" at 2630,520 h30
  text "C1" at 1176.57,457.51 h30
  text "C1" at 2796.57,457.51 h30
  text "R7" at 1369.14,448.08 h30
  text "R7" at 2989.14,448.08 h30
  text "REF2" at 1460,340 h30
  text "REF2" at 3080,340 h30
  text "C3" at 1190,290 h30
  text "C3" at 2810,290 h30
  text "For evaluation only; not FCC approved for resale." at 210,230 h20
  text "For evaluation only; not FCC approved for resale." at 1830,230 h20
  text "IN-" at 620,180 h30
  text "GND" at 890,180 h30
  text "VS" at 1070,180 h30
  text "IN-" at 2240,180 h30
  text "GND" at 2510,180 h30
  text "VS" at 2690,180 h30
  text "D2" at 30,110 h30
  text "D2" at 1650,110 h30
  text ".Layer_Name" at 577,-858.49 h60
Bottom Overlay:
  text ".Layer_Name" at 577,-858.49 h60
Top Paste:
  text ".Layer_Name" at 577,-858.49 h60
Bottom Paste:
  text ".Layer_Name" at 577,-858.49 h60
Top Solder:
  text ".Layer_Name" at 577,-858.49 h60
  text ".Layer_Name" at 577,-858.49 h60
Bottom Solder:
  text ".Layer_Name" at 577,-858.49 h60
Drill Guide:
  text ".Layer_Name" at 577,-858.49 h60
M1 Board Outline:
  lines w10: 0,1250 3200,1250 ; 1600,0 1600,2500 ; 0,0 3200,0 3200,2500 0,2500 0,0
  text ".Layer_Name" at 577,-858.49 h60
M2 Board Dimensions:
  rectangle: 0,-275 125,-150
  rectangle: 125,-400 500,-275
  lines w7: 0,-275 1000,-275 ; 125,-400 125,-150 ; 250,-400 250,-150 ; 500,-400 500,-150 ; 750,-400 750,-150 ; 0,-400 1000,-400 1000,-150 0,-150 0,-400
  text ".Layer_Name" at 577,-858.49 h60
M3 3D STEP Top:
  text ".Layer_Name" at 577,-858.49 h60
M4 3D STEP Bottom:
  text ".Layer_Name" at 577,-858.49 h60
M5 Assembly Top:
  lines w10: -292,-930.17 6308,-930.17 ; -292,-726.83 6310,-726.83 ; -292,-523.5 -292,-1133.5 3713,-1133.5 6310,-1133.5 6310,-523.5 -291.5,-523.5 -291.5,-1133.5 1284,-1133.5 ; 2173,-1133.5 2173,-523.5 ; 3440,-726.83 3440,-523.5 ; 4280,-726.83 4280,-523.5 ; 4902,-1140 4902,-937.17
  text "COMPONENTS MARKED 'DNP' SHOULD NOT BE POPULATED." at 1153.5,-318.5 h60
  text "ASSEMBLY VARIANT:" at 1153,-434 h60
  text ".VariantName" at 2189,-434 h60
  text "PCB VIEWED FROM TOP SIDE" at -228.5,-655.67 h60
  text "BOARD #:" at 2248,-655.67 h60
  text ".PRJ_Number" at 2793.5,-655.67 h60
  text "REV:" at 3638,-655.67 h60
  text ".PCB_Rev" at 3929.5,-655.67 h60
  text "SVN REV:" at 4476,-655.67 h60
  text ".VersionControl_RevNumber" at 4982,-655.67 h60
  text "TID #:" at 2248,-859 h60
  text ".TID" at 2793.5,-859 h60
  text "PLOT NAME =" at -228.5,-1064.34 h60
  text ".plot_File_Name" at 577,-1064.34 h60
  text "GENERATED    :" at 2250,-1064.34 h60
  text ".Print_Date" at 3119.5,-1064.34 h60
  text ".Print_Time" at 3848.5,-1064.34 h60
  text "TEXAS INSTRUMENTS" at 5113,-1064.34 h60
M6 Assembly Bottom:
  lines w10: -292.5,-727.33 6309.5,-727.33 ; -290.5,-930.67 6309.5,-930.67 ; 1115.5,-1140.5 1115.5,-937.67 ; 1737.5,-727.33 1737.5,-524 ; 2577.5,-727.33 2577.5,-524 ; 3844.5,-1134 3844.5,-524 ; 4733.5,-1134 6309,-1134 6309,-524 -292.5,-524 -292.5,-1134 2304.5,-1134 6309.5,-1134 6309.5,-524
  text "COMPONENTS MARKED 'DNP' SHOULD NOT BE POPULATED." at 6102,-318 h60
  text ".VariantName" at 5058,-434 h60
  text "ASSEMBLY VARIANT:" at 6097,-434 h60
  text ".VersionControl_RevNumber" at 1035.5,-656.17 h60
  text "SVN REV:" at 1541.5,-656.17 h60
  text ".PCB_Rev" at 2088,-656.17 h60
  text "REV:" at 2379.5,-656.17 h60
  text ".PRJ_Number" at 3224,-656.17 h60
  text "BOARD #:" at 3769.5,-656.17 h60
  text "PCB VIEWED FROM BOTTOM SIDE" at 6246,-656.17 h60
  text ".PRJ_Number" at 3224,-859.5 h60
  text "TID #:" at 3769.5,-859.5 h60
  text "TEXAS INSTRUMENTS" at 904.5,-1064.84 h60
  text ".Print_Time" at 2169,-1064.84 h60
  text ".Print_Date" at 2898,-1064.84 h60
  text "GENERATED    :" at 3767.5,-1064.84 h60
  text ".plot_File_Name" at 5440.5,-1064.84 h60
  text "PLOT NAME =" at 6246,-1064.84 h60
M9 Title Sheet:
  drawing of 57 lines, arcs and shapes, not listed
  text "1" at 739.84,8036.5 h70
  text "2" at 3235.5,8036.5 h70
  text "3" at 5724.84,8036.5 h70
  text "4" at 8231.51,8036.5 h70
  text "5" at 10730.5,8036.5 h70
  text "6" at 13235.5,8036.5 h70
  text "A" at -416.5,6893.5 h70
  text "A" at 14383.5,6893.5 h70
  text "B" at -416.5,4513.5 h70
  text "B" at 14383.5,4513.5 h70
  text "C" at -416.5,2138.5 h70
  text "C" at 14383.5,2138.5 h70
  text "PROJECT TITLE:" at 11343.5,277.5 h45
  text ".PRJ_Title" at 11393.5,144.17 h70
  text "DESIGNED FOR:" at 11343.5,-23.5 h45
  text ".PRJ_Customer" at 11393.5,-163.5 h70
  text "D" at -416.5,-231.5 h70
  text "D" at 14383.5,-231.5 h70
  text "FILE NAME:" at 11343.5,-323.5 h45
  text ".PCB_File_Name_No_Path" at 11393.5,-443.5 h70
  text "Texas Instruments (TI) and/or its licensors do not warrant the accuracy or completeness of this specification" at 6374,-605.34 h45
  text "ENGINEER:" at 11343.5,-613.5 h45
  text "LAYOUT BY:" at 12848.5,-613.5 h45
  text "or any information contained therein. TI and/or its licensors do not warrant that this design will meet" at 6329.01,-718 h45
  text ".PRJ_Engineer" at 11393.5,-768.49 h70
  text ".PCB_Layout" at 12899,-768.49 h70
  text "the specifications, will be suitable for your application or fit for any particular purpose, or will operate in" at 6329.01,-830.67 h45
  text ".Layer_Name" at 577,-858.49 h60
  text "ALTIUM DESIGNER VERSION:" at 12848.5,-923.5 h45
  text "an implementation. TI and/or its licensors do not warrant that the design is production worthy. You should" at 6329.01,-943.33 h45
  text "completely validate and test your design implementation to confirm the system functionality for your application." at 6374,-1056 h45
  text ".print_Scale" at 11393.5,-1056.83 h70
  text ".Application_BuildNumber" at 12899,-1056.83 h70
  text "1" at 739.84,-1263.5 h70
  text "2" at 3235.5,-1263.5 h70
  text "3" at 5724.84,-1263.5 h70
  text "4" at 8231.51,-1263.5 h70
  text "5" at 10730.5,-1263.5 h70
  text "6" at 13235.5,-1263.5 h70
M10 Fab Notes:
  drawing of 185 lines, arcs and shapes, not listed
  text "DESIGN INFORMATION" at 12381.02,5910 h60
  text "MIN. TRACK WIDTH:" at 11736.46,5730 h60
  text "8" at 12832.7,5730 h60
  text "MIL" at 12987.46,5730 h60
  text "MIN. CLEARANCE:" at 11736.46,5598 h60
  text "0.2" at 12772.7,5598 h60
  text "mm" at 12987.46,5598 h60
  text "MIN. VIA PAD SIZE:" at 11736.46,5466 h60
  text "24" at 12802.71,5466 h60
  text "MIL" at 12987.46,5466 h60
  text "0.05mm (2MIL)" at 12431.46,5324.29 h60
  text "MINIMUM ANNULAR RING" at 11407.23,5320 h60
  text "EXTERNAL" at 13139.46,5320 h60
  text "PER" at 11607.23,5202 h60
  text "IPC-D-275 CLASS 2 LEVEL C" at 11827.23,5202 h60
  text "MIL, HOLES" at 13315.46,5089.71 h60
  text "+/-" at 12923,5089 h60
  text "+/-" at 13777,5089 h60
  text "REGISTRATION TOLERANCES:" at 11407.23,5084 h60
  text "METAL" at 12607,5084 h60
  text "5" at 13183.2,5084 h60
  text "3" at 14016.2,5084 h60
  text "MIL" at 14132.46,5084 h60
  text "MATERIAL:" at 11332.46,4874.54 h60
  text "FR-4 High Tg" at 12318.9,4734.21 h60
  text "FR-408" at 11753.46,4725.64 h60
  text "X" at 12165.46,4725.64 h60
  text "OTHER" at 13241.46,4725.64 h60
  text "62 MIL (1.6mm) +/-10%" at 12073.56,4562.92 h60
  text "THICKNESS:" at 11407.23,4558.64 h60
  text "X" at 11945.4,4558.64 h60
  text "OTHER" at 13358.46,4558.64 h60
  text "TOLERANCE:" at 11407.23,4400.64 h60
  text "X" at 12246.53,4400.64 h60
  text "ANSI IPC-6012 TYPE 3 CLASS 2" at 12433.48,4400.64 h60
  text "OTHER +/-" at 12433.46,4244.64 h60
  text "BOW & TWIST:" at 11407.23,4087.64 h60
  text "X" at 12246.53,4087.64 h60
  text "ANSI IPC-6012 TYPE 3 CLASS 2" at 12433.48,4087.64 h60
  text "OTHER +/-" at 12433.46,3929.13 h60
  text "DRILLING:" at 11332.46,3790.64 h60
  text "REFERENCE:" at 11407.23,3673.64 h60
  text "X" at 12055.46,3673.64 h60
  text "AS SHOWN" at 12242.46,3673.64 h60
  text "X" at 12956.46,3673.64 h60
  text "NC_DRILL FILES" at 13093.46,3673.64 h60
  text "PTH MIN COPPER THICKNESS:" at 11407.23,3515.64 h60
  text "X" at 12757.46,3515.64 h60
  text "1MIL" at 12894.46,3515.64 h60
  text "OTHER" at 13391.46,3515.64 h60
  text "BOARD FINISH:" at 11332.46,3356.64 h60
  text "X" at 12430,3240 h60
  text "SILKSCREEN:" at 11487.68,3238.64 h60
  text "TOP" at 12562.46,3238.64 h60
  text "BOTTOM" at 13073.46,3238.64 h60
  text "SILKSCREEN COLOR:" at 11487.68,3071.64 h60
  text "X" at 12435.42,3071.64 h60
  text "WHITE" at 12562.46,3071.64 h60
  text "OTHER" at 13073.46,3071.64 h60
  text "SOLDER RESIST COLOR:" at 11487.68,2901.64 h60
  text "X" at 12055.42,2742.44 h60
  text "GREEN" at 12182.46,2742.44 h60
  text "BLUE" at 12773.46,2742.44 h60
  text "OTHER" at 13311.46,2742.44 h60
  text "IMMERSION GOLD (ENIG)" at 12393.46,2553.92 h60
  text "ENEPIG" at 13731,2550.64 h60
  text "SURFACE FINISH:" at 11332.46,2549.64 h60
  text "X" at 12206.51,2549.64 h60
  text "IMM. TIN/SILVER OR EQUIV" at 11662,2392.64 h60
  text "OTHER" at 13093.46,2392.64 h60
  text "ARRAY/PANEL:" at 11332.46,2213.64 h60
  text "CUT AND TRIM PER MECH LAYER 1" at 12393.46,2209.35 h60
  text "N.C. ROUTE" at 12393.46,2057.64 h60
  text "X" at 13072.46,2057.64 h60
  text "V. SCORE" at 13259.46,2057.64 h60
  text "CERTIFICATION:" at 11332.46,1920.64 h60
  text "MATERIALS AND WORKMANSHIP FOR ALL PCBS" at 12057.46,1920.64 h60
  text "TO MEET OR EXCEED THE REQUIREMENTS OF:" at 12057.46,1822.64 h60
  text "X" at 11683.96,1686.13 h60
  text "ANSI IPC-A-600F CLASS ->" at 11822.96,1686.13 h60
  text "X" at 13462.02,1686.13 h60
  text "2" at 13580.96,1686.14 h60
  text "1" at 13265.96,1684.64 h60
  text "3" at 13934.96,1684.64 h60
  text "X" at 11686.02,1526.64 h60
  text "UL 94V-0" at 11822.96,1526.64 h60
  text "X" at 12498.02,1526.64 h60
  text "RoHS" at 12634.96,1526.64 h60
  text "OTHER" at 13279.36,1526.64 h60
  text "PER ORDER" at 13676.42,1526.64 h60
  text "ADDITIONAL REQUIREMENTS:" at 11332.46,1385.64 h60
  text "MICROSECTION:" at 11407.23,1270.64 h60
  text "YES" at 12312.96,1270.64 h60
  text "REQUIRED" at 13174.46,1114.49 h60
  text "BARE BOARD ELEC. TEST:" at 11407.23,1111.64 h60
  text "NONE" at 12712.96,1111.64 h60
  text "X" at 13047.46,1111.64 h60
  text "PER ORDER" at 13766.46,1111.64 h60
  text "MANUFACTURER'S UL:" at 11407.23,954.64 h60
  text "RAIL" at 12572.96,950.35 h60
  text "METAL" at 13064.77,950.35 h60
  text "X" at 13440,950 h60
  text "SILK" at 13576.46,950.35 h60
  text ".Layer_Name" at 577,-858.49 h60
M11 Gerber Information:
  lines w10: -292,-930.17 6308,-930.17 ; -292,-726.83 6310,-726.83 ; -292,-523.5 -292,-1133.5 3713,-1133.5 6310,-1133.5 6310,-523.5 -291.5,-523.5 -291.5,-1133.5 1284,-1133.5 ; 2173,-1133.5 2173,-523.5 ; 3440,-726.83 3440,-523.5 ; 4280,-726.83 4280,-523.5 ; 4902,-1140 4902,-937.17
  text "ALL ARTWORK VIEWED FROM TOP SIDE" at -228.5,-655.67 h60
  text "BOARD #:" at 2248,-655.67 h60
  text ".PRJ_Number" at 2793.5,-655.67 h60
  text "REV:" at 3638,-655.67 h60
  text ".PCB_Rev" at 3929.5,-655.67 h60
  text "SVN REV:" at 4476,-655.67 h60
  text ".VersionControl_RevNumber" at 4982,-655.67 h60
  text "LAYER NAME =" at -228.5,-858.49 h60
  text "TID #:" at 2248,-859 h60
  text ".TID" at 2793.5,-859 h60
  text "PLOT NAME =" at -228.5,-1064.34 h60
  text ".plot_File_Name" at 577,-1064.34 h60
  text "GENERATED    :" at 2250,-1064.34 h60
  text ".Print_Date" at 3119.5,-1064.34 h60
  text ".Print_Time" at 3848.5,-1064.34 h60
  text "TEXAS INSTRUMENTS" at 5113,-1064.34 h60
M12 Stackup:
  drawing of 191 lines, arcs and shapes, not listed
  text "Layer" at 9790.34,7830 h60
  text "Name" at 10200.26,7830 h60
  text "Material" at 11130,7830 h60
  text "Thickness" at 11989.77,7830 h60
  text "Constant" at 12639.6,7830 h60
  text "Board Layer Stack" at 13209.46,7830 h60
  text "1" at 9790.34,7710 h60
  text "Top Overlay" at 10200.26,7710 h60
  text "2" at 9790.34,7590 h60
  text "Top Solder" at 10200.26,7590 h60
  text "Solder Resist" at 11130,7590 h60
  text "0.40mil" at 11989.77,7590 h60
  text "3.5" at 12639.6,7590 h60
  text "3" at 9790.34,7470 h60
  text "Top Layer" at 10200.26,7470 h60
  text "Copper" at 11130,7470 h60
  text "1.40mil" at 11989.77,7470 h60
  text "4" at 9790.34,7350 h60
  text "Dielectric1" at 10200.26,7350 h60
  text "FR-4" at 11130,7350 h60
  text "59.20mil" at 11989.77,7350 h60
  text "4.8" at 12639.6,7350 h60
  text "5" at 9790.34,7230 h60
  text "Bottom Layer" at 10200.26,7230 h60
  text "Copper" at 11130,7230 h60
  text "1.40mil" at 11989.77,7230 h60
  text "6" at 9790.34,7110 h60
  text "Bottom Solder" at 10200.26,7110 h60
  text "Solder Resist" at 11130,7110 h60
  text "0.40mil" at 11989.77,7110 h60
  text "3.5" at 12639.6,7110 h60
  text "7" at 9790.34,6990 h60
  text "Bottom Overlay" at 10200.26,6990 h60
  text ".Layer_Name" at 577,-858.49 h60
M13 Component Bodies Top:
  text ".Layer_Name" at 577,-858.49 h60
M14 Component Bodies Bottom:
  text ".Layer_Name" at 577,-858.49 h60
M15 Courtyards Top:
  text ".Layer_Name" at 577,-858.49 h60
M16 Courtyards Bottom:
  text ".Layer_Name" at 577,-858.49 h60
Drill Drawing:
  circle w10: c5683.72,3141.96 r27.63
  lines w10: 0,1250 3200,1250 ; 1600,0 1600,2500 ; 5656.09,2990.02 5711.34,2990.02 5711.34,3045.27 5656.09,3045.27 5656.09,2990.02 ; 5656.09,3293.91 5711.34,3293.91 5683.72,3238.66 5656.09,3293.91
  lines w12: 5606,2952.72 7584.02,2952.72 ; 5606,3325.68 7584.02,3325.68 ; 5943.86,2828.4 5943.86,3450 ; 6275.86,2828.4 6275.86,3450 ; 6912.43,2828.4 6912.43,3450 ; 7171.57,2828.4 7171.57,3450 ; 5606,2828.4 7584.02,2828.4 7584.02,3450 5606,3450 5606,2828.4
  text "Symbol" at 5680.59,3362.98 h72
  text "Quantity" at 5981.16,3362.98 h72
  text "Finished Hole Size" at 6313.16,3362.98 h72
  text "Plated" at 6949.72,3362.98 h72
  text "Hole Type" at 7208.86,3362.98 h72
  text "8" at 5981.16,3238.66 h60
  text "16.00mil (0.406mm)" at 6313.16,3238.66 h60
  text "PTH" at 6949.72,3238.66 h60
  text "Round" at 7208.86,3238.66 h60
  text "12" at 5981.16,3114.34 h60
  text "28.00mil (0.711mm)" at 6313.16,3114.34 h60
  text "PTH" at 6949.72,3114.34 h60
  text "Round" at 7208.86,3114.34 h60
  text "36" at 5981.16,2990.02 h60
  text "63.00mil (1.600mm)" at 6313.16,2990.02 h60
  text "PTH" at 6949.72,2990.02 h60
  text "Round" at 7208.86,2990.02 h60
  text "56 Total" at 5981.16,2865.7 h60
  text ".Layer_Name" at 577,-858.49 h60

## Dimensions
0,0 to 1600,-140 on Drill Drawing
0,-400 to 1000,-400 on M2 Board Dimensions
0,0 to -20,2500 on M2 Board Dimensions
0,-10 to 3200,-10 on M2 Board Dimensions
0,0 to 0,1250 on Drill Drawing
1600,2500 to 1750,2650 on Drill Drawing
3200,1260 to 3350,1410 on Drill Drawing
